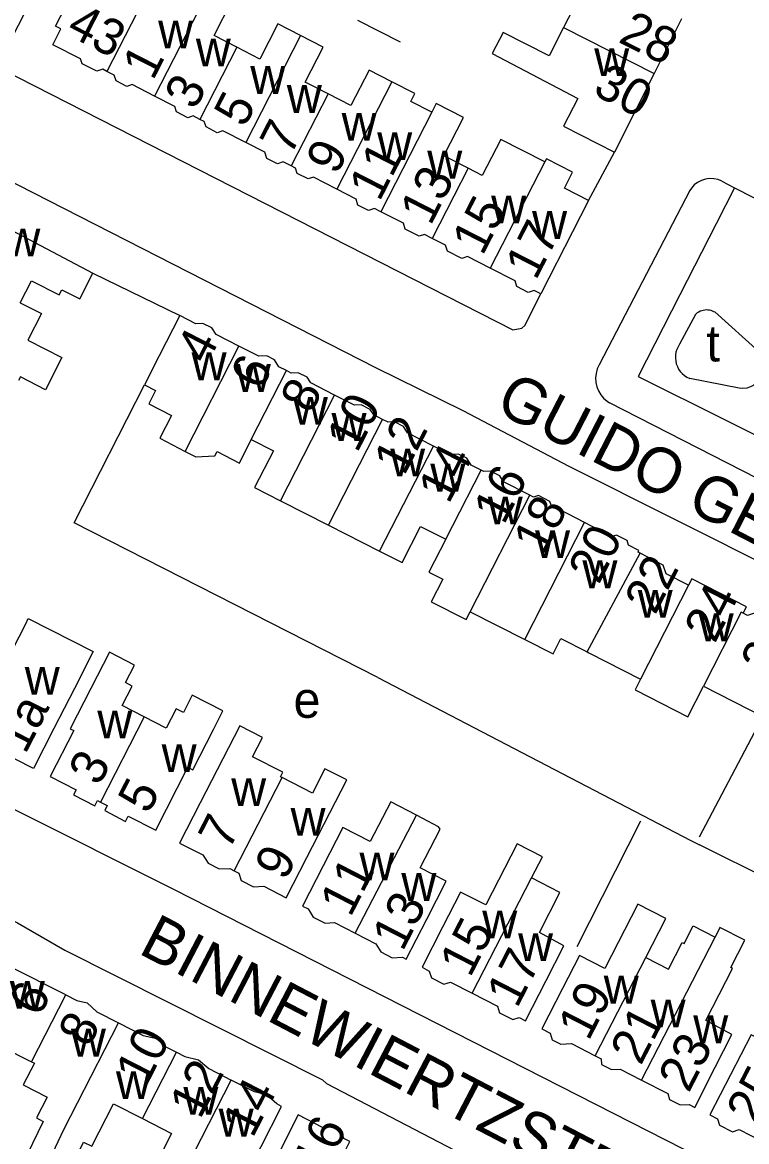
# Model space of a CAD drawing. Extents: x 159700 to 161346, y 381730 to 382922.
# Drawn here: x 161020.3 to 161100.4, y 382436.1 to 382559.9 of the extents above; entities that cross this region are included whole.
import ezdxf

# ---------------------------------------------------------------- set-up
doc = ezdxf.new("R2010")
doc.units = 0
for name, color, linetype in [('BLT_Basislijn', 7, 'Continuous'), ('BLT_Bebouwing', 7, 'Continuous'), ('BLT_Centroide', 7, 'Continuous'), ('BLT_Huisnummer', 7, 'Continuous'), ('BLT_Huisnummer_ tussenligend', 7, 'Continuous'), ('BLT_Onderverdeling_panden', 7, 'Continuous'), ('BLT_Straatnaam', 7, 'Continuous')]:
    doc.layers.add(name, color=color, linetype=linetype)

msp = doc.modelspace()

# ---------------------------------------------------------------- linework, layer by layer
at = {"layer": 'BLT_Basislijn'}
for p, q in [((161062.11, 382557.7), (161057.41, 382560.11)), ((161082.91, 382540.19), (161085.77, 382545.52)), ((161097.65, 382542.33), (161099.06, 382541.6)), ((161094.1, 382541.31), (161084.07, 382522.01)), ((161099.06, 382541.6), (161097.02, 382537.62)), ((161099.06, 382541.6), (161113.5, 382534.2)), ((161097.02, 382537.62), (161093, 382529.76)), ((161028.1, 382532.15), (161037.72, 382527.46)), ((161094.73, 382527.6), (161092.96, 382524.3)), ((161096.87, 382527.86), (161101.78, 382523.44)), ((161099.56, 382519.43), (161094.1, 382520.49)), ((161130.9, 382494.46), (161085.21, 382517.82)), ((161098.16, 382515.85), (161115.01, 382507.42)), ((161095.19, 382469.83), (161101.62, 382482.06)), ((161088.65, 382471.55), (161081.63, 382457.64)), ((161117.63, 382457.72), (161095.18, 382468.95))]:
    msp.add_line(p, q, dxfattribs=at)
for points in [[(161024.71, 382568.32), (161023.67, 382567.09), (161017.93, 382555.74), (161017.98, 382554.76), (161074.53, 382525.9), (161075.55, 382526.06), (161075.87, 382526.38), (161077.62, 382529.86)], [(161011.13, 382546.35), (161004.14, 382532.72), (161001.78, 382527.68), (160984.45, 382493.29), (160983.66, 382490.77), (161037.03, 382464.02), (161097.28, 382433.33), (161117.83, 382422.87), (161120.84, 382421.08), (161151.41, 382405.63), (161152.84, 382405.02), (161153.31, 382404.99), (161153.57, 382405.21), (161167.8, 382433.33), (161179.15, 382454.6), (161181.26, 382459.06), (161181.21, 382459.73), (161169.51, 382465.52), (161164.37, 382468.48), (161163.6, 382468.73), (161139.77, 382480.75)], [(161011.13, 382546.35), (161059.35, 382521.71), (161069.03, 382516.96), (161080.74, 382510.81), (161104.09, 382499.08), (161138.78, 382481.25), (161139.77, 382480.75)], [(161097.65, 382542.33), (161097.22, 382542.5), (161096.76, 382542.59), (161096.29, 382542.61), (161095.83, 382542.55), (161095.38, 382542.4), (161094.97, 382542.19), (161094.6, 382541.91), (161094.28, 382541.57), (161094.1, 382541.31)], [(161093, 382529.76), (161088.39, 382520.74), (161098.16, 382515.85)], [(161094.73, 382527.6), (161094.85, 382527.7), (161094.97, 382527.8), (161095.11, 382527.89), (161095.26, 382527.97), (161095.42, 382528.03), (161095.58, 382528.08), (161095.75, 382528.11), (161095.93, 382528.12), (161096.1, 382528.11), (161096.27, 382528.09), (161096.43, 382528.05), (161096.59, 382528), (161096.73, 382527.93), (161096.87, 382527.86)], [(161092.96, 382524.3), (161092.8, 382524.02), (161092.67, 382523.72), (161092.57, 382523.41), (161092.52, 382523.09), (161092.52, 382522.77), (161092.55, 382522.45), (161092.61, 382522.14), (161092.73, 382521.84), (161092.87, 382521.55), (161093.05, 382521.28), (161093.27, 382521.04), (161093.51, 382520.84), (161093.79, 382520.65), (161094.1, 382520.49)], [(161101.78, 382523.44), (161102.02, 382523.1), (161102.2, 382522.72), (161102.31, 382522.31), (161102.36, 382521.88), (161102.32, 382521.45), (161102.21, 382521.04), (161102.05, 382520.67), (161101.82, 382520.33), (161101.53, 382520.03), (161101.19, 382519.77), (161100.8, 382519.58), (161100.39, 382519.45), (161099.97, 382519.41), (161099.56, 382519.43)], [(161084.07, 382522.01), (161083.87, 382521.56), (161083.74, 382521.07), (161083.69, 382520.58), (161083.71, 382520.08), (161083.82, 382519.59), (161084.01, 382519.13), (161084.26, 382518.7), (161084.58, 382518.32), (161084.96, 382517.99), (161085.21, 382517.82)], [(161059.62, 382487.43), (161026.05, 382504.54), (161033.81, 382519.81)], [(161059.62, 382487.43), (161094.23, 382469.43), (161095.18, 382468.95)], [(161006.2, 382467.14), (161019.79, 382460.32), (161025.02, 382457.3), (161053.5, 382442.94), (161053.96, 382442.53), (161071.63, 382433.33), (161121.07, 382408.34)]]:
    msp.add_lwpolyline(points, dxfattribs=at)
at = {"layer": 'BLT_Bebouwing'}
for p, q in [((161093.19, 382560.28), (161090.16, 382554.24)), ((161090.16, 382554.24), (161085.77, 382545.52)), ((161082.91, 382540.19), (161077.62, 382529.86)), ((161054.16, 382504.27), (161059.82, 382501.41)), ((161095.62, 382486.48), (161102.32, 382483.06))]:
    msp.add_line(p, q, dxfattribs=at)
for points in [[(161029.67, 382554.46), (161029.22, 382554.7), (161028.55, 382554.48), (161026.93, 382555.31), (161026.75, 382555.85), (161023.7, 382557.41), (161024.59, 382559.16), (161024, 382559.47), (161027.76, 382566.76), (161024.71, 382568.32)], [(161080.35, 382566.78), (161078.31, 382567.81), (161076.83, 382564.9), (161081.72, 382562.43), (161080.14, 382559.31)], [(161044.05, 382557.13), (161041.52, 382558.43), (161043.49, 382562.28), (161041, 382563.56)], [(161051.07, 382558.44), (161048.57, 382559.72), (161046.58, 382555.83), (161044.05, 382557.13)], [(161080.14, 382559.31), (161078.56, 382556.2), (161073.46, 382558.78), (161072.27, 382556.44), (161081.73, 382551.47), (161080.15, 382548.4), (161085.77, 382545.52)], [(161054.11, 382551.97), (161051.58, 382553.26), (161053.58, 382557.16), (161051.07, 382558.44)], [(161034.94, 382551.73), (161032.46, 382553), (161031.88, 382552.81), (161030.68, 382553.43), (161030.48, 382554.05), (161029.67, 382554.46)], [(161061.18, 382553.33), (161058.65, 382554.62), (161056.63, 382550.68), (161054.11, 382551.97)], [(161065.59, 382549.95), (161063.25, 382551.15), (161063.7, 382552.03), (161061.18, 382553.33)], [(161039.96, 382549.16), (161039.21, 382549.55), (161038.62, 382549.35), (161037.38, 382549.99), (161037.19, 382550.58), (161034.94, 382551.73)], [(161069.59, 382543.76), (161066.92, 382545.13), (161069.1, 382549.37), (161066.08, 382550.91), (161065.59, 382549.95)], [(161045.02, 382546.62), (161042.5, 382547.91), (161041.85, 382547.69), (161040.63, 382548.32), (161040.43, 382548.92), (161039.96, 382549.16)], [(161078.06, 382544.45), (161073.2, 382546.94), (161071.16, 382542.96), (161069.59, 382543.76)], [(161050.03, 382544.02), (161049.17, 382544.46), (161048.51, 382544.25), (161047.36, 382544.84), (161047.14, 382545.53), (161045.02, 382546.62)], [(161082.91, 382540.19), (161080.24, 382541.56), (161081.14, 382543.31), (161078.25, 382544.8), (161078.06, 382544.45)], [(161055.09, 382541.43), (161052.5, 382542.76), (161051.9, 382542.57), (161050.69, 382543.19), (161050.5, 382543.78), (161050.03, 382544.02)], [(161059.96, 382538.95), (161059.25, 382539.31), (161058.58, 382539.1), (161057.42, 382539.69), (161057.21, 382540.35), (161055.09, 382541.43)], [(161011.84, 382533.05), (161013.49, 382536.33), (161013.78, 382536.18), (161014.28, 382537.17), (161014.07, 382538.01), (161014.44, 382538.74), (161015.62, 382539.12), (161019.32, 382537.28), (161019.11, 382536.9), (161028.1, 382532.15)], [(161065.63, 382536), (161064.79, 382536.43), (161064.19, 382536.24), (161062.65, 382537.03), (161062.45, 382537.68), (161059.96, 382538.95)], [(161072.05, 382532.71), (161069.53, 382534), (161068.89, 382533.79), (161067.31, 382534.6), (161067.1, 382535.25), (161065.63, 382536)], [(161020.1, 382528.88), (161021.33, 382531.32), (161024.39, 382529.77), (161024.67, 382530.32), (161026.69, 382529.3), (161028.1, 382532.15)], [(161077.62, 382529.86), (161076.89, 382530.24), (161076.24, 382530.03), (161074.99, 382530.67), (161074.78, 382531.31), (161072.05, 382532.71)], [(161020.1, 382528.88), (161022.43, 382527.7), (161020.92, 382524.73), (161024.68, 382522.82), (161022.89, 382519.27), (161020.11, 382520.68), (161019.9, 382520.27)], [(161037.72, 382527.46), (161035.44, 382523.01), (161033.81, 382519.81)], [(161044.27, 382524.08), (161041.73, 382525.37), (161041.26, 382526.1), (161040.29, 382526.59), (161039.5, 382526.55), (161037.72, 382527.46)], [(161049.51, 382521.39), (161048.68, 382521.81), (161048.19, 382522.57), (161047.34, 382523), (161046.46, 382522.96), (161044.27, 382524.08)], [(161054.84, 382518.68), (161052.23, 382520.01), (161051.82, 382520.65), (161050.83, 382521.15), (161050.05, 382521.11), (161049.51, 382521.39)], [(161033.81, 382519.81), (161035.05, 382519.18), (161034.29, 382517.7), (161036.82, 382516.41), (161035.53, 382513.89), (161038.33, 382512.45)], [(161060.14, 382515.97), (161059.18, 382516.47), (161058.78, 382517.07), (161057.78, 382517.59), (161057.05, 382517.55), (161054.84, 382518.68)], [(161065.76, 382513.04), (161062.9, 382514.5), (161062.44, 382515.2), (161061.46, 382515.7), (161060.75, 382515.66), (161060.14, 382515.97)], [(161038.33, 382512.45), (161039.51, 382511.85), (161041.61, 382511.95), (161041.85, 382512.42), (161044.33, 382511.16), (161045.63, 382513.77)], [(161045.63, 382513.77), (161048.08, 382512.52), (161045.99, 382508.44), (161048.86, 382506.98)], [(161071.03, 382510.37), (161069.94, 382510.93), (161069.46, 382511.68), (161068.55, 382512.15), (161067.6, 382512.1), (161065.76, 382513.04)], [(161076.42, 382507.6), (161073.51, 382509.09), (161073.09, 382509.74), (161072.09, 382510.25), (161071.35, 382510.21), (161071.03, 382510.37)], [(161082.47, 382504.57), (161078.77, 382506.49), (161078.63, 382506.92), (161077.37, 382507.56), (161076.84, 382507.39), (161076.42, 382507.6)], [(161048.86, 382506.98), (161054.16, 382504.27)], [(161059.82, 382501.41), (161062.29, 382500.15), (161064.33, 382504.15), (161067.13, 382502.72)], [(161088.6, 382501.18), (161088.39, 382501.3), (161088.48, 382501.48), (161087.34, 382502.06), (161087.17, 382502.59), (161086, 382503.18), (161085.49, 382503.02), (161085, 382503.27), (161082.47, 382504.57)], [(161067.13, 382502.72), (161065.27, 382499.09), (161066.81, 382498.3), (161065.53, 382495.81), (161069.38, 382493.84), (161069.83, 382494.71)], [(161093.95, 382497.64), (161091.48, 382498.9), (161091.16, 382499.88), (161088.6, 382501.18)], [(161100, 382494.55), (161100.37, 382495.26), (161094.32, 382498.35), (161093.95, 382497.64)], [(161017.74, 382487.61), (161020.7, 382493.39), (161020.98, 382493.95), (161028.16, 382490.32), (161026.07, 382486.23)], [(161069.83, 382494.71), (161075.87, 382491.63)], [(161106.49, 382491.23), (161103.18, 382492.92), (161102.83, 382494.03), (161101.58, 382494.66), (161100.48, 382494.31), (161100, 382494.55)], [(161075.87, 382491.63), (161078.99, 382490.04), (161079.86, 382491.74), (161082.74, 382490.27)], [(161033.8, 382483.09), (161031.37, 382484.34), (161032.47, 382486.48), (161031.71, 382486.87), (161032.72, 382488.82), (161029.96, 382490.24), (161027.9, 382486.23), (161025.62, 382481.78), (161026.02, 382481.57), (161023.41, 382476.49), (161026.28, 382475.02), (161025.99, 382474.45), (161028.32, 382473.25), (161028.62, 382473.84), (161028.96, 382473.67)], [(161082.74, 382490.27), (161082.95, 382490.16), (161088.65, 382487.25)], [(161088.65, 382487.25), (161088.05, 382486.08), (161093.89, 382483.1), (161095.62, 382486.48)], [(161026.07, 382486.23), (161023.82, 382481.81), (161021.54, 382477.36), (161015.75, 382480.34), (161016.5, 382481.8), (161015.12, 382482.5)], [(161028.96, 382473.67), (161029.71, 382473.27), (161029.43, 382472.72), (161031.74, 382471.53), (161032.03, 382472.11), (161035.06, 382470.56), (161038.63, 382477.51), (161039.18, 382477.23), (161041.46, 382481.67), (161042.48, 382483.76), (161039.1, 382485.47), (161038.12, 382483.57), (161037.33, 382483.97), (161036.23, 382481.84), (161033.8, 382483.09)], [(161049.04, 382476.38), (161048.86, 382476.47), (161049.11, 382476.96), (161045.78, 382478.67), (161046.88, 382480.8), (161044.37, 382482.09), (161039.99, 382473.58), (161037.71, 382469.13), (161040.26, 382467.82), (161040.86, 382466.89), (161042.08, 382466.27), (161043.24, 382466.32), (161043.74, 382466.07)], [(161043.74, 382466.07), (161044.24, 382465.81), (161044.5, 382465), (161045.87, 382464.3), (161047.03, 382464.36), (161049.49, 382463.09), (161051.77, 382467.54), (161056.19, 382476.13), (161053.77, 382477.33), (161052.4, 382474.66), (161049.04, 382476.38)], [(161063.91, 382472.23), (161061.04, 382473.7), (161058.78, 382469.31), (161055.76, 382470.86), (161053.58, 382466.61), (161051.29, 382462.16), (161051.9, 382461.85), (161052.48, 382460.95), (161053.78, 382460.28), (161054.83, 382460.33), (161057.11, 382459.16)], [(161057.11, 382459.16), (161059.39, 382457.99), (161059.96, 382457.1), (161061.22, 382456.45), (161062.33, 382456.51), (161062.76, 382456.28), (161065.05, 382460.73), (161067.16, 382464.92), (161064.31, 382466.39), (161066.51, 382470.66), (161066.32, 382470.94), (161063.91, 382472.23)], [(161076.6, 382465.27), (161077.81, 382467.61), (161075.03, 382469.04), (161071.56, 382462.28), (161068.77, 382463.7), (161066.78, 382459.83), (161064.5, 382455.39), (161065.3, 382454.97), (161065.55, 382454.21), (161066.9, 382453.51), (161067.66, 382453.76), (161070.05, 382452.53)], [(161070.05, 382452.53), (161072.83, 382451.1), (161073.06, 382450.37), (161074.53, 382449.61), (161075.23, 382449.84), (161075.93, 382449.48), (161078.22, 382453.93), (161080.19, 382457.77), (161077.48, 382459.23), (161079.75, 382463.65), (161076.6, 382465.27)], [(161089.24, 382456.47), (161091.45, 382460.77), (161088.35, 382462.37), (161084.7, 382455.27), (161081.91, 382456.68), (161080.04, 382453.03), (161077.75, 382448.58), (161078.67, 382448.11), (161078.9, 382447.38), (161079.85, 382446.89), (161081.01, 382446.95), (161083.65, 382445.6)], [(161088.76, 382442.91), (161091.66, 382441.42), (161091.87, 382440.77), (161093.03, 382440.17), (161094.02, 382440.22), (161094.64, 382439.9), (161096.92, 382444.35), (161098.75, 382447.97), (161095.88, 382449.49), (161098.84, 382455.26), (161098.64, 382455.36), (161100.2, 382458.38), (161097.44, 382459.8), (161096.9, 382458.74)], [(161089.24, 382456.47), (161091.74, 382455.18), (161093.26, 382458.14), (161093.47, 382458.03), (161094.47, 382459.99), (161096.9, 382458.74)], [(161025.13, 382452.33), (161018.9, 382455.47), (161016.62, 382451.02), (161015.14, 382448.16), (161012.73, 382443.46), (161015.68, 382441.95), (161018.06, 382446.6), (161021.34, 382444.93)], [(161025.13, 382452.33), (161026.35, 382451.72), (161027.47, 382451.45), (161028.57, 382450.47), (161030.96, 382449.25)], [(161030.96, 382449.25), (161033.68, 382447.85), (161035.19, 382447.52), (161036.17, 382446.61), (161037.36, 382446)], [(161107.99, 382447.69), (161105.16, 382449.09), (161103.78, 382446.41), (161100.88, 382447.91), (161098.6, 382443.51), (161096.31, 382439.06), (161097.15, 382438.63), (161097.37, 382437.95), (161098.82, 382437.2), (161099.57, 382437.44), (161102.14, 382436.12)], [(161037.36, 382446), (161038.27, 382445.54), (161039.78, 382445.16), (161040.93, 382444.19), (161043.42, 382442.91)], [(161083.65, 382445.6), (161084.3, 382445.26), (161084.33, 382444.64), (161085.45, 382444.07), (161086.42, 382444.11), (161088.76, 382442.91)], [(161021.34, 382444.93), (161021.65, 382444.77), (161020.43, 382442.38), (161023.05, 382441.03), (161021.87, 382438.73), (161022.21, 382438.56), (161022.61, 382438.35), (161020.85, 382434.68), (161023.07, 382433.55)], [(161035.06, 382426.52), (161037.28, 382425.38), (161039.48, 382429.68), (161040.09, 382429.37), (161042.12, 382433.33), (161042.56, 382434.18), (161044.23, 382433.33), (161045.29, 382432.8), (161045.56, 382433.33), (161046.71, 382435.56), (161048.98, 382440.01), (161048.47, 382440.28), (161047.31, 382441.28), (161045.97, 382441.61), (161043.42, 382442.91)], [(161023.07, 382433.55), (161025.3, 382432.4), (161027.07, 382436.07), (161027.99, 382435.6), (161030.39, 382440.3), (161033.6, 382438.66)], [(161033.6, 382438.66), (161036.81, 382437.01), (161034.92, 382433.33), (161034.39, 382432.29), (161035.03, 382431.96), (161032.83, 382427.66), (161035.06, 382426.52)], [(161051.68, 382426.71), (161054.25, 382431.66), (161055.11, 382433.33), (161056.53, 382436.11), (161055.85, 382436.46), (161055.61, 382437.2), (161054.54, 382437.75), (161053.5, 382437.69), (161050.83, 382439.06), (161048.55, 382434.61), (161047.9, 382433.33), (161044.05, 382425.83), (161047.16, 382424.23), (161049.1, 382428.02), (161051.68, 382426.71)]]:
    msp.add_lwpolyline(points, dxfattribs=at)
at = {"layer": 'BLT_Onderverdeling_panden'}
for p, q in [((161041, 382563.56), (161034.94, 382551.73)), ((161033.71, 382562.37), (161029.67, 382554.46)), ((161080.14, 382559.31), (161090.16, 382554.24)), ((161051.07, 382558.44), (161045.02, 382546.62)), ((161044.05, 382557.13), (161039.96, 382549.16)), ((161061.18, 382553.33), (161055.09, 382541.43)), ((161054.11, 382551.97), (161050.03, 382544.02)), ((161065.59, 382549.95), (161059.96, 382538.95)), ((161069.59, 382543.76), (161065.63, 382536)), ((161078.06, 382544.45), (161072.05, 382532.71)), ((161038.33, 382512.45), (161044.27, 382524.08)), ((161045.63, 382513.77), (161049.51, 382521.39)), ((161048.86, 382506.98), (161054.84, 382518.68)), ((161054.16, 382504.27), (161060.14, 382515.97)), ((161059.82, 382501.41), (161065.76, 382513.04)), ((161067.13, 382502.72), (161071.03, 382510.37)), ((161069.83, 382494.71), (161076.42, 382507.6)), ((161075.87, 382491.63), (161082.47, 382504.57)), ((161082.74, 382490.27), (161088.6, 382501.18)), ((161093.95, 382497.64), (161088.65, 382487.25)), ((161033.8, 382483.09), (161028.96, 382473.67)), ((161043.74, 382466.07), (161049.04, 382476.38)), ((161057.11, 382459.16), (161063.91, 382472.23)), ((161070.05, 382452.53), (161076.6, 382465.27)), ((161088.76, 382442.91), (161096.9, 382458.74)), ((161083.65, 382445.6), (161089.24, 382456.47)), ((161021.34, 382444.93), (161025.13, 382452.33)), ((161033.6, 382438.66), (161037.36, 382446))]:
    msp.add_line(p, q, dxfattribs=at)
for points in [[(161100, 382494.55), (161099.78, 382494.66), (161095.62, 382486.48)], [(161023.07, 382433.55), (161024.91, 382437.46), (161030.96, 382449.25)], [(161035.06, 382426.52), (161038.52, 382433.33), (161043.42, 382442.91)]]:
    msp.add_lwpolyline(points, dxfattribs=at)

# ---------------------------------------------------------------- texts
at = {"layer": 'BLT_Centroide'}
for s, p in [('w', (161035.33, 382557.02)), ('w', (161039.5, 382555.02)), ('w', (161083.54, 382553.94)), ('w', (161045.52, 382551.98)), ('w', (161049.56, 382549.88)), ('w', (161055.61, 382546.81)), ('w', (161059.55, 382544.66)), ('w', (161065.08, 382542.62)), ('w', (161072.14, 382537.67)), ('w', (161076.67, 382535.94)), ('w', (161018.45, 382534)), ('t', (161095.94, 382522.39)), ('w', (161039.03, 382520.31)), ('w', (161043.92, 382519.03)), ('w', (161050.23, 382515.39)), ('w', (161054.5, 382513.61)), ('w', (161060.98, 382509.69)), ('w', (161065.42, 382508)), ('w', (161071.77, 382504.38)), ('w', (161077, 382500.64)), ('w', (161082.23, 382497.31)), ('w', (161088.34, 382494.05)), ('w', (161095.08, 382491.45)), ('w', (161020.59, 382485.53)), ('e', (161050.3, 382482.98)), ('w', (161028.61, 382480.7)), ('w', (161035.72, 382476.97)), ('w', (161043.41, 382473.23)), ('w', (161049.97, 382469.95)), ('w', (161057.59, 382465)), ('w', (161062.22, 382462.73)), ('w', (161071.16, 382458.58)), ('w', (161075.12, 382456.09)), ('w', (161084.59, 382451.38)), ('w', (161018.94, 382450.8)), ('w', (161089.77, 382448.75)), ('w', (161094.48, 382447)), ('w', (161025.69, 382445.52)), ('w', (161030.67, 382440.81)), ('w', (161038.12, 382439.09)), ('w', (161042.02, 382436.67))]:
    msp.add_text(s, height=4, dxfattribs=at).set_placement(p)
at = {"layer": 'BLT_Huisnummer'}
for s, rotation, p in [('43', 332.883, (161025.04, 382558.6)), ('28', 333.1474, (161086.08, 382557.77)), ('1', 62.8835, (161034.76, 382553.36)), ('30', 332.2254, (161083.24, 382552.02)), ('5', 62.8851, (161044.88, 382548.14)), ('9', 62.8845, (161055.06, 382542.9)), ('13', 62.8758, (161065.44, 382537.3)), ('17', 62.8784, (161077.08, 382531.27)), ('4', 62.9558, (161040.74, 382521.95)), ('8', 62.9532, (161052.22, 382516.49)), ('12', 62.9545, (161062.53, 382509.65)), ('16', 62.9534, (161073.55, 382504.22)), ('20', 62.9561, (161084.04, 382497.63)), ('24', 62.9561, (161096.86, 382491.11)), ('1a', 62.7944, (161020.65, 382478.86)), ('3', 62.7991, (161028.81, 382475.33)), ('7', 62.7944, (161043.15, 382468.21)), ('11', 62.7944, (161056.58, 382460.82)), ('15', 62.7944, (161069.81, 382454.15)), ('6', 62.8826, (161022.21, 382449.78)), ('19', 62.7894, (161082.9, 382447.14)), ('10', 62.8872, (161034, 382442.1)), ('23', 62.6516, (161093.98, 382441.41)), ('14', 62.6181, (161045.77, 382436.41)), ('16', 62.6181, (161053.56, 382432.26))]:
    msp.add_text(s, height=4, rotation=rotation, dxfattribs=at).set_placement(p)
at = {"layer": 'BLT_Huisnummer_ tussenligend'}
for s, rotation, p in [('3', 62.8835, (161039.42, 382550.09)), ('7', 62.8851, (161049.96, 382545.03)), ('11', 62.8845, (161059.79, 382539.97)), ('15', 62.8758, (161071.19, 382533.98)), ('6', 62.9558, (161046.71, 382519.09)), ('10', 62.9532, (161057.32, 382512.17)), ('14', 62.9545, (161067.45, 382506.52)), ('18', 62.9534, (161077.96, 382500.85)), ('22', 62.9561, (161090.27, 382494.26)), ('26', 62.9561, (161103.08, 382487.48)), ('5', 62.7991, (161034.26, 382472.22)), ('9', 62.7944, (161049.38, 382464.85)), ('13', 62.7944, (161062.35, 382457.04)), ('17', 62.7944, (161075, 382450.76)), ('21', 62.7894, (161088.68, 382444.44)), ('8', 62.8826, (161027.66, 382446.41)), ('12', 62.8872, (161039.97, 382438.48)), ('25', 62.6516, (161101.51, 382437.77))]:
    msp.add_text(s, height=4, rotation=rotation, dxfattribs=at).set_placement(p)
at = {"layer": 'BLT_Straatnaam'}
for s, rotation, p in [('GUIDO GEZELLESTRAAT', 332.7898, (161072.41, 382516.97)), ('BINNEWIERTZSTRAAT', 332.4539, (161033.01, 382457))]:
    msp.add_text(s, height=5, rotation=rotation, dxfattribs=at).set_placement(p)

doc.saveas('drawing.dxf')
